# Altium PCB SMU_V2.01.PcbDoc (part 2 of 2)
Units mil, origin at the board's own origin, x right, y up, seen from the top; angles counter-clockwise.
Board outline 8661.42 x 7437.01 mil, 4 copper layers (Component Side, Ground Plane, Power Plane, Solder Side), stack 33.234 mil thick; 247 components, 163 nets, 805 pads, 762 vias.
Unrouted connection lines stored in the file: 6.
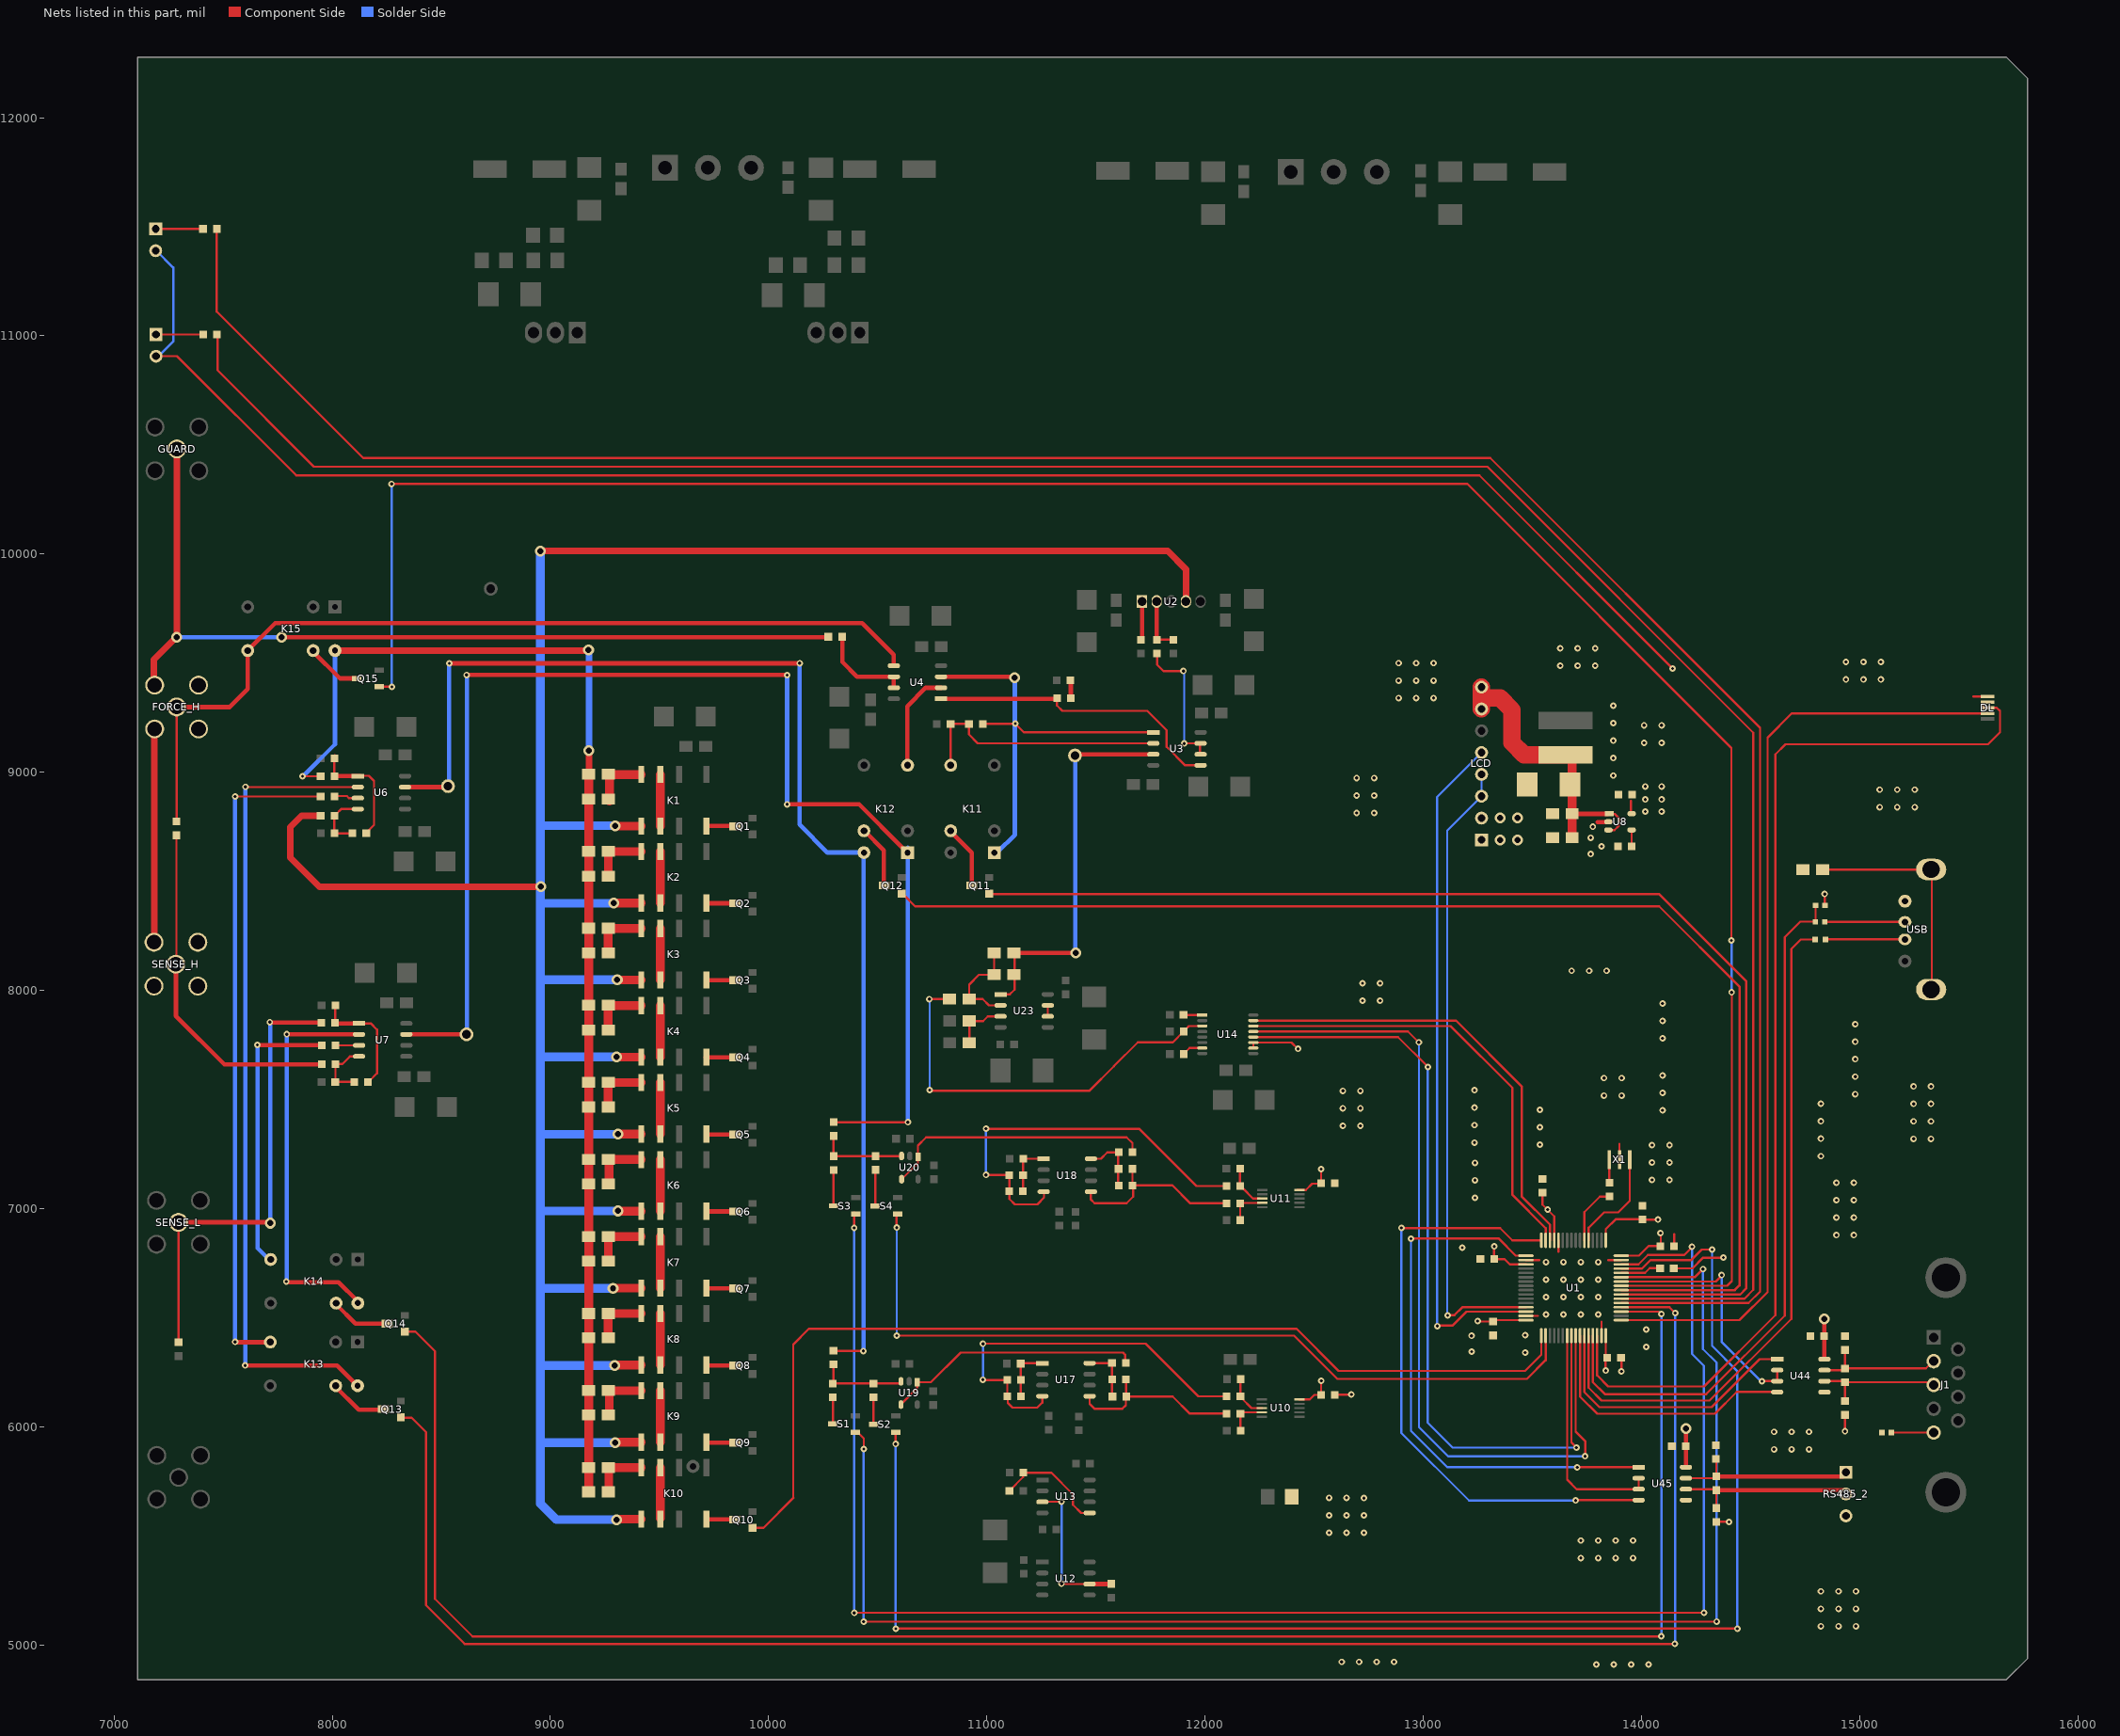
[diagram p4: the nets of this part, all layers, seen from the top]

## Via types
v1: diameter 30/30 (per signal layer), hole 14, Component Side to Solder Side, 662 vias
v2: diameter 50, hole 28, Component Side to Solder Side, 70 vias
v3: diameter 30, hole 14, Component Side to Solder Side, 26 vias
v4: diameter 39.37, hole 29.53, Component Side to Solder Side, 2 vias
v5: diameter 66.93, hole 47.24, Component Side to Solder Side, 2 vias

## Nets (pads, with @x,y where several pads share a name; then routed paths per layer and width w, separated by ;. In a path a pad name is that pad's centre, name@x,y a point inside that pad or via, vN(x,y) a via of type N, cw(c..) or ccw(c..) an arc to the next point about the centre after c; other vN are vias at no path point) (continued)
CTRL10: Q10.1 U1.33 | length 4625.3
  Component Side w10: Q10.1@9920.57,5537.65 9976.4,5537.65 10113.13,5674.38 ; Q10.1@9922.12,5537.11 Q10.1@9922.12,5551.99 ; 10112.55,5673.29 10112.55,6377.54 10185.04,6450.03 12418.3,6450.03 12612.01,6256.32 13466.42,6256.32 13540.97,6330.87 U1.33@13540.97,6418.24
CTRL11: Q11.1 U1.55 | length 5625.4
  Component Side w10: Q11.1@11014.47,8436.12 11020.61,8442.25 14080.45,8442.25 14478.93,8043.78 14478.93,8042.97 14479.29,8042.61 14479.29,6633.68 14452.82,6607.22 U1.55@13907.11,6607.22
CTRL12: Q12.1 U1.56 | length 5930.3
  Component Side w10: Q12.1@10614.72,8442.38 10671.36,8385.73 14080.95,8385.74 14449,8017.69 14449,6648.43 14427.48,6626.9 U1.56@13907.11,6626.9
CTRL13: Q13.1 U1.52 | length 8504
  Component Side w10: Q13.1@8316.05,6042.29 8363.72,6042.29 8429.56,5976.45 8429.56,5182.38 8606.5,5005.45 v3@14152.06,5005.45 ; U1.52@13907.11,6548.16 14128.51,6548.16 v3@14154.38,6522.29
  Solder Side w10: v3@14154.38,5005.85 v3(14154.38,6521.19)
  other v3: 14152.57,5005.85
CTRL14: Q14.1 U1.51 | length 8666.1
  Component Side w10: Q14.1@8326.42,6436.35 8381.6,6436.35 8470.69,6347.26 8470.69,5212.23 8643.14,5039.78 14081.06,5039.78 v3@14091.75,5050.47 ; U1.51@13907.11,6528.48 14079.18,6528.48 v3@14089.4,6518.25
  Solder Side w10: v3@14091.54,5050.7 v3(14091.54,6517.14)
  other v3: 14090.71,5040.17
CTRL15: Q15.1 U1.57 | length 10596.9
  Component Side w10: Q15.1@8214.96,9392.83 v3@8277.84,9392.83 ; v3(8272.01,10321.59) 13202.4,10321.59 14412.19,9111.8 v1@14412.19,8228.18 ; U1.57@13907.11,6646.59 14392.55,6646.59 14413.69,6667.73 v1@14413.69,7988.82
  Solder Side w10: v3(8272.93,9391.66) v3@8272.93,10323.43 ; v1(14413.05,7991.51) v1@14413.05,8232.41
  other v1: 14412.19,8229.76
D1: K1.8 Q1.3 | length 133.6
  Component Side w20: K1.8@9715.55,8753.74 Q1.3@9849.19,8753.74
D2: K2.8 Q2.3 | length 130.3
  Component Side w20: K2.8@9715.03,8399.71 Q2.3@9845.34,8399.71
D3: K3.8 Q3.3 | length 130.4
  Component Side w20: K3.8@9714.93,8046.63 Q3.3@9845.34,8046.63
D3V3: C1.2 C2.2 C3.2 C4.2 C5.2 C6.2 C22.2 C29.2 C81.2 C85.2 C108.2 LED0.2 LED1.2 R42.1 R102.2 R105.2 U1.1 U1.13 U1.19 U1.32 U1.48 U1.64 U8.5 U10.10 U11.10 U14.10 U14.11 U44.8 U45.8 | length 10716.3
  Component Side w10: LED1.2@7176.54,10907.22 7288.28,10907.22 7835.2,10360.31 13256.88,10360.31 v1(14141.88,9475.31) ; U14.10@12221.05,7736.31 U14.11@12221.05,7758.94 ; U14.11@12226.3,7761.51 12395.95,7761.51 12424.84,7732.62 v1@12426.19,7732.62 ; U11.10@12421.52,7085.54 12461.73,7085.54 12490.94,7114.75 C85.2@12523.99,7114.75 ; U10.10@12432.09,6125.59 12479.89,6125.59 12500.92,6146.61 C81.2@12515.07,6146.61 ; C85.2@12531.5,7116.98 v1@12531.5,7175.83 ; C81.2@12531.71,6147.25 v1@12531.71,6210.47 ; v1@13245.25,6482.49 C6.2@13319.59,6482.49 ; C2.2@13312.76,6768.97 13372.99,6768.97 13396.94,6745.01 U1.19@13470.11,6745.01 ; C6.2@13319.59,6489.11 U1.32@13470.11,6489.11 ; C2.2@13324.77,6770.14 v1@13324.77,6828.08 ; C1.2@13546.28,7074.6 13546.28,7018.74 13600.03,6964.99 U1.13@13600.03,6855.25 ; v1(13835.74,6258.05) C5.2@13835.74,6314.15 ; C5.2@13836.25,6305.29 U1.48@13836.25,6418.24 ; U1.1@13836.25,6855.25 13836.25,6906.38 13881.15,6951.29 C4.2@14009.16,6951.29 ; U1.64@13907.11,6784.38 13987.94,6784.38 14032.89,6829.34 C3.2@14084.69,6829.34 ; U8.5@13950.9,8809.48 13950.9,8869.84 ; C4.2@14003.81,6950.29 v1@14078.83,6950.29 ; C3.2@14088.76,6836.88 v1@14088.76,6883.52 ; R105.2@14342.63,5565.07 v1@14398.65,5565.07 ; v2(14838.42,6495.31) v2@14838.42,6508.77 ; R42.1@14839.75,8391.23 v1(14839.75,8442.22) ; v1(14932.63,5979.56) R102.2@14932.63,6055.07
  Component Side w20: U45.8@14203.42,5815.31 v2(14203.42,5991.84) ; U44.8@14838.42,6310.31 v2(14838.42,6495.31)
  Solder Side w10: LED1.2@7192.45,10906.75 7203.88,10906.75 7271.25,10974.11 7271.25,11313 LED0.2@7193.23,11391.03
  other v1: 14401.39,5564.22 12532.32,6210.98 13248.99,6485.31 13325.59,6826.87 14087.17,6887.98 14075.08,6949.95 13569.87,6996 12531.7,7180.98 12426.15,7732.55 14016.88,8820.31 14091.88,8820.31 14016.88,8875.31 14091.88,8875.31 14016.88,8935.31 14091.88,8935.31
D4: K4.8 Q4.3 | length 133.8
  Component Side w20: K4.8@9711.55,7693.54 Q4.3@9845.34,7693.54
D5: K5.8 Q5.3 | length 132.6
  Component Side w20: K5.8@9712.77,7340.46 Q5.3@9845.34,7340.46
D5V0: C57.2 C58.2 C59.1 L2.2 LCD.7 LCD.8 U8.1 U8.3 | length 1367.8
  Component Side w10: U8.3@13844.6,8734.68 13876.25,8734.68 13896.88,8755.31 13896.88,8790.31 13877.71,8809.48 U8.1@13844.6,8809.48
  Component Side w22: C58.2@13682.71,8809.48 U8.1@13844.6,8809.48
  Component Side w40: C57.2@13682.34,8700.76 13682.34,8935.31 L2.2@13682.34,9070.07
  Component Side w80: LCD.7@13266.88,9290.31 LCD.8@13266.88,9390.31 ; 13266.88,9340.31 13351.88,9340.31 13406.88,9285.31 13406.88,9135.31 13461.88,9080.31 L2.2@13651.88,9080.31
D6: K6.8 Q6.3 | length 126.8
  Component Side w20: K6.8@9718.57,6987.37 Q6.3@9845.34,6987.37
D7: K7.8 Q7.3 | length 128.9
  Component Side w20: K7.8@9716.44,6634.29 Q7.3@9845.34,6634.29
D8: K8.8 Q8.3 | length 127
  Component Side w20: K8.8@9718.38,6281.21 Q8.3@9845.34,6281.21
D9: K9.8 Q9.3 | length 132
  Component Side w20: K9.8@9713.35,5928.12 Q9.3@9845.34,5928.12
D10: K10.8 Q10.3 | length 128
  Component Side w20: K10.8@9715.55,5576.99 Q10.3@9843.53,5576.99
D11: K11.5 Q11.3 | length 272.2
  Component Side w10: K11.5@10834.46,8728.35 K11.5@10834.46,8732.05
  Component Side w20: K11.5@10834.46,8728.35 10930.62,8632.19 Q11.3@10930.62,8499.67
D12: K12.5 Q12.3 | length 284.1
  Component Side w10: K12.5@10436.55,8732.05 K12.5@10438.01,8732.05
  Component Side w20: K12.5@10438.01,8732.05 10528.04,8642.01 Q12.3@10528.04,8486.75
D13: K13.5 Q13.3 | length 267.4
  Component Side w10: K13.5@8014.82,6185.08 K13.5@8014.82,6187.86
  Component Side w20: K13.5@8014.82,6185.08 8120.68,6079.23 Q13.3@8235.57,6079.23
D14: K14.5 Q14.3 | length 284.6
  Component Side w20: K14.5@8016.68,6562.69 8106.59,6472.77 Q14.3@8264.05,6472.77
D15: K15.5 Q15.3 | length 253.5
  Component Side w20: K15.5@7910.7,9554.75 8035.22,9430.23 Q15.3@8112.6,9430.23
DAC1_FSYNC: U1.41 U14.13 | length 3927.6
  Component Side w10: U14.13@12222.43,7811.9 12929.54,7811.9 v1@12979.23,7762.21 ; U1.41@13698.45,6418.24 13698.45,5978.74 13741.88,5935.31 v1(13741.88,5865.31)
  Solder Side w10: v1@12980.14,7761.37 12980.14,5999.26 13114.08,5865.31 v1(13741.88,5865.31)
  other v1: 12979.57,7762.59
DAC1_RESET: U1.14 U14.15 | length 2110.4
  Component Side w10: U14.15@12224.6,7862.29 13149.46,7862.29 13450.72,7561.03 13450.72,7056.85 13580.34,6927.22 U1.14@13580.34,6855.25
DAC1_SCLK: U1.40 U14.12 | length 3735.5
  Component Side w10: U14.12@12224.06,7786.7 12884.54,7786.7 v1@13020.01,7651.24 ; U1.40@13678.77,6418.24 13678.77,5928.43 v1(13701.88,5905.31)
  Solder Side w10: v1@13020.04,7651.46 13020.04,6019.85 13134.58,5905.31 v1(13701.88,5905.31)
  other v1: 13020.67,7649.88
DAC1_SDATA: U1.15 U14.14 | length 2059.5
  Component Side w10: U14.14@12225.14,7837.1 13125.18,7837.1 ; 13127.08,7835.11 13408.8,7553.4 13408.8,7062.49 13560.66,6910.63 U1.15@13560.66,6855.25
DGND: C1.1 C2.1 C3.1 C4.1 C5.1 C6.1 C22.1 C23.1 C29.1 C57.1 C58.1 C59.2 C81.1 C85.1 C108.1 DL.5 L1.2 L3.2 LCD.1 LCD.2 R2.2 R66.1 R101.2 R104.2 RS485_2.3 U1.12 U1.18 U1.31 U1.47 U1.63 U8.2 U44.5 U45.5 USB.4 X1.2 | length 897.6
  Component Side w10: C81.1@12594.7,6147.25 v1@12672.07,6147.25 ; U1.31@13470.11,6508.79 13525.37,6508.79 ; U1.18@13470.11,6764.7 13531.27,6764.7 ; 13619.71,6802.48 U1.12@13619.71,6855.25 ; U1.47@13816.56,6418.24 13816.56,6481.79 ; 13847.49,6764.7 U1.63@13907.11,6764.7 ; X1.2@13899.11,7225.16 13899.11,7297.18 ; v1(13907.96,6253.87) C5.1@13907.96,6317.13 ; C3.1@14149.66,6828.63 14149.66,6882.15 ; 14166.08,6726.9 14233.71,6726.9 14282.33,6775.51 v1@14373.8,6775.51 ; 15520.28,9346.96 DL.5@15585.53,9346.96
  Component Side w20: 13798.66,8772.08 U8.2@13844.6,8772.08
  other v1: 13792.56,4911.52 13872.56,4911.52 13952.56,4911.52 14032.56,4911.52 12625.86,4923 12705.86,4923 12785.86,4923 12865.86,4923 14822.53,5086.38 14902.53,5086.38 14982.53,5086.38 14822.53,5166.38 14902.53,5166.38 14982.53,5166.38 14822.53,5246.38 14902.53,5246.38 14982.53,5246.38 13721.63,5399.14 13801.63,5399.14 13881.63,5399.14 13961.63,5399.14 13721.63,5479.14 13801.63,5479.14 13881.63,5479.14 13961.63,5479.14 12568.37,5515.09 12648.37,5515.09 12728.37,5515.09 12568.37,5595.09 12648.37,5595.09 12728.37,5595.09 12728.25,5673.54 12568.37,5675.09 12648.37,5675.09 14607.34,5897.3 14687.34,5897.3 14767.34,5897.3 14607.34,5977.3 14687.34,5977.3 14767.34,5977.3 12670.6,6148.64 13466.88,6340.31 13221.75,6344.34 14021.33,6366.39 13220.96,6417.42 13466.88,6420.31 14021.33,6446.39 13561.88,6515.31 13641.88,6515.31 13721.88,6515.31 13801.88,6515.31 13561.88,6595.31 13641.88,6595.31 13721.88,6595.31 13801.88,6595.31 13561.88,6675.31 13641.88,6675.31 13721.88,6675.31 13801.88,6675.31 13561.88,6755.31 13641.88,6755.31 13721.88,6755.31 13801.88,6755.31 14374.93,6776.65 13178.69,6821.71 14893.33,6879.01 14973.33,6879.01 14893.33,6959.01 14973.33,6959.01 14893.33,7039.01 14973.33,7039.01 13236.88,7050.31 14893.33,7119.01 14973.33,7119.01 13236.88,7130.31 14048.35,7131.47 14128.35,7131.47 13236.88,7210.31 14048.35,7211.47 14128.35,7211.47 14822.19,7240.68 14048.35,7291.47 14128.35,7291.47 13534.13,7293.67 13234.52,7303.01 15246.88,7320.31 15326.88,7320.31 14822.19,7320.68 13534.13,7373.67 12631.88,7380.31 12711.88,7380.31 13234.52,7383.01 15246.88,7400.31 15326.88,7400.31 14822.19,7400.68 14096.2,7450.86 13534.13,7453.67 12631.88,7460.31 12711.88,7460.31 13234.52,7463.01 15246.88,7480.31 15326.88,7480.31 14822.19,7480.68 13828.57,7518.66 13908.57,7518.66 14979.77,7525.18 14096.2,7530.86 12631.88,7540.31 12711.88,7540.31 13234.52,7543.01 15246.88,7560.31 15326.88,7560.31 13828.57,7598.66 13908.57,7598.66 14979.77,7605.18 14096.2,7610.86 14979.77,7685.18 14979.77,7765.18 14096.2,7780.86 14979.77,7845.18 14096.2,7860.86 14096.2,7940.86 12721.88,7953.43 12801.88,7953.43 12721.88,8033.43 12801.88,8033.43 13679.84,8090.23 13759.84,8090.23 13839.84,8090.23 13766.88,8625.31 13816.88,8660.31 13766.88,8700.31 13776.88,8750.31 12694.62,8813.79 12774.62,8813.79 15091.88,8840.31 15171.88,8840.31 15251.88,8840.31 12694.62,8893.79 12774.62,8893.79 15091.88,8920.31 15171.88,8920.31 15251.88,8920.31 12694.62,8973.79 12774.62,8973.79 13870.46,8985.13 13870.46,9065.13 14011.88,9135.31 14091.88,9135.31 13870.46,9145.13 14011.88,9215.31 14091.88,9215.31 13870.46,9225.13 13870.46,9305.13 12886.88,9340.31 12966.88,9340.31 13046.88,9340.31 12886.88,9420.31 12966.88,9420.31 13046.88,9420.31 14936.88,9425.31 15016.88,9425.31 15096.88,9425.31 13627.78,9488.72 13707.78,9488.72 13787.78,9488.72 12886.88,9500.31 12966.88,9500.31 13046.88,9500.31 14936.88,9505.31 15016.88,9505.31 15096.88,9505.31 13627.78,9568.72 13707.78,9568.72 13787.78,9568.72
  other v2: 13351.88,8690.31 13431.88,8690.31 13351.88,8790.31 13431.88,8790.31
DUT_VOLTAGE: K12.1 R51.2 T2.1 U7.7 | length 6180.8
  Component Side w10: R51.2@10297.56,7396.42 v3@10634.24,7396.42
  Component Side w20: U7.7@8339.58,7798.88 T2.1@8615.03,7798.88 ; v3(8615.67,9446.19) v3@10079.09,9446.19 ; v3(10084.09,8853.31) 10414.46,8853.31 K12.1@10611.71,8656.06
  Solder Side w20: T2.1@8616.66,7799.23 v3@8616.66,9446.22 ; v3@10084.41,8856.18 v3(10084.41,9445.92) ; v3@10637.68,7394.96 K12.1@10637.68,8654.16
  other v3: 10637.98,7396.46
FB_R_T1: C70.1 C71.1 C72.1 C73.1 C74.1 C75.1 C76.1 C77.1 C78.1 C79.1 K15.6 R19.2 R31.1 R32.1 R33.1 R34.1 R35.1 R36.1 R37.1 R38.1 R39.1 R40.1 | length 5739.7
  Component Side w10: v3@7867.94,8981.55 R19.2@7948.53,8981.55
  Component Side w30: K15.6@8012.65,9557.88 v2@9173.85,9557.88 ; R31.1@9171.24,8985.77 9176.58,8991.11 v2(9176.56,9099.22)
  Component Side w40: C79.1@9175.42,5705.38 R40.1@9175.42,5813.12 C78.1@9175.42,6055.22 R39.1@9175.42,6166.28 C77.1@9175.42,6407.94 R38.1@9175.42,6519.44 C76.1@9175.42,6760.67 R37.1@9175.42,6872.6 C75.1@9175.42,7113.4 R36.1@9175.42,7225.76 C74.1@9175.42,7466.13 R35.1@9175.42,7578.92 C73.1@9175.42,7818.86 R34.1@9175.42,7932.09 C72.1@9175.42,8171.58 R33.1@9175.42,8285.25 C71.1@9175.42,8524.31 R32.1@9175.42,8638.41 C70.1@9175.42,8877.04 R31.1@9175.42,8991.57
  Solder Side w20: v3@7866.28,8982.22 8012.65,9128.59 K15.6@8012.65,9557.88
  Solder Side w30: v2@9175.92,9558.76 9176.56,9558.12 v2(9176.56,9099.22)
  other v2: 9174.48,9560.15
  other v3: 7864.07,8981.28
FB_R_T2: K1.5 K2.5 K3.5 K4.5 K5.5 K6.5 K7.5 K8.5 K9.5 K10.5 R21.2 U2.4 | length 13617.1
  Component Side w30: R21.2@7939.8,8801.07 7860.21,8801.07 7808.19,8749.06 7808.19,8607.99 7941.02,8475.16 v2@8953.23,8475.16 ; v2@8955.66,10013.74 11828.42,10013.74 11911.99,9930.18 U2.4@11911.99,9782.7
  Component Side w40: v2@9287.6,6635.91 K7.5@9416.34,6635.91 ; v2@9288.99,8400.76 K2.5@9416.34,8400.76 ; v2@9289.28,6282.93 K8.5@9416.34,6282.93 ; v2@9296.82,5929.96 K9.5@9416.34,5929.96 ; v2@9297.25,7694.82 K4.5@9416.34,7694.82 ; v2@9298.95,8753.74 K1.5@9416.34,8753.74 ; v2@9304.27,5576.99 K10.5@9416.34,5576.99 ; v2@9307.92,8047.79 K3.5@9416.34,8047.79 ; v2@9309.83,6988.88 K6.5@9416.34,6988.88 ; v2@9314.01,7341.85 K5.5@9416.34,7341.85
  Solder Side w40: v2@8953.9,10014.45 8953.9,6989.61 ; 8954.79,8755.61 v2@9300.6,8755.61 ; 8956.15,6281.23 v2(9293.52,6281.23) ; 8957.46,6634.94 v2(9286.79,6634.94) ; 8960.46,7695.1 v2(9303.13,7695.1) ; 8960.49,8399.92 v2(9289.6,8399.92) ; 8962.72,8049.77 v2(9306.02,8049.77) ; 8963.99,7341.39 v2(9308.9,7341.39) ; v2(9296.41,5927.52) 8953.9,5927.52 ; v2(9303.13,5574.77) 9027.3,5574.77 8953.9,5648.16 8953.9,5927.52 ; v2(9308.9,6989.61) 8953.9,6989.61 ; 8953.9,5927.52 8953.9,6989.61
  other v2: 8956.65,8475.63 9296.1,8754.49 8953.63,10013.91
FH_OUT: FORCE_H.1 K15.4 R76.1 U4.5 | length 4177.8
  Component Side w10: R76.1@7286.86,8778.52 FORCE_H.1@7286.86,9298.99 ; K15.4@7612.65,9557.88 K15.4@7612.9,9558.12
  Component Side w20: FORCE_H.1@7286.86,9298.99 7530.07,9298.99 7612.9,9381.82 7612.9,9558.12 7738.67,9683.9 10427.91,9683.9 10572.74,9539.06 U4.5@10572.74,9490.63
GUARD: FORCE_H.2 GUARD.1 R28.2 SENSE_H.2 | length 5137.4
  Component Side w10: SENSE_H.2@7175.5,8220.98 SENSE_H.2@7184.03,8220.98 ; SENSE_H.2@7383.96,8011.56 SENSE_H.2@7383.96,8020.19
  Component Side w20: v2@7762.69,9619.66 R28.2@10273.67,9619.66
  Component Side w30: FORCE_H.2@7177.03,9209.76 7184.03,9202.76 SENSE_H.2@7184.03,8220.98 ; FORCE_H.2@7182.05,9394.91 7182.05,9516.65 7288.07,9622.67 GUARD.1@7288.07,10482.17
  Solder Side w20: v2@7282.04,9619.6 v2(7768.41,9619.6)
  other v2: 7287.71,9619.68
LED0: R68.2 U1.53 | length 11483.7
  Component Side w10: R68.2@7470.77,11490.82 7470.77,11111.24 8141.7,10440.31 13306.88,10440.31 14543.28,9203.91 14543.28,6620.21 14490.92,6567.85 U1.53@13907.11,6567.85
LED1: R69.2 U1.54 | length 11066.6
  Component Side w10: R69.2@7474.11,11007.05 7474.11,10842.18 7915.98,10400.31 13293.67,10400.31 14512.4,9181.58 14512.4,6628.06 14471.87,6587.53 U1.54@13907.11,6587.53
NetC7_1: C7.1 R46.2 U10.4 | length 184.1
  Component Side w10: C7.1@12161.61,5985.45 12161.61,6066.65 U10.4@12264.51,6066.65
NetC8_1: C8.1 R47.2 U11.4 | length 161.1
  Component Side w10: C8.1@12160.93,6944.16 R47.2@12160.93,7023.76 ; R47.2@12168.75,7026.48 U11.4@12250.26,7026.48
NetC20_2: C20.2 R10.2 U2.2 | length 254.1
  Component Side w10: R10.2@11779.77,9607.52 C20.2@11855.36,9607.52
  Component Side w20: R10.2@11777.83,9608.74 U2.2@11777.83,9787.27
NetC21_1: C21.1 R16.2 | length 86.5
  Component Side w20: R16.2@11384.47,9333.72 C21.1@11384.47,9420.26
NetC23_2: C23.2 U8.4 | length 72.4
  Component Side w10: C23.2@13954.72,8663.27 U8.4@13954.72,8735.63
NetC30_1: C30.1 C31.2 R19.1 U6.1 | length 516.8
  Component Side w10: C31.2@8008.6,9074.08 C31.2@8011.71,9077.19 ; R19.1@8009.95,8982.56 C31.2@8009.95,9064.12 ; U6.1@8125.98,8984.01 8167.34,8984.01 8191.55,8959.8 8191.55,8758.68 C30.1@8165.54,8732.67
  Component Side w20: R19.1@8009.13,8982.4 U6.1@8126.51,8982.4
NetC30_2: C30.2 C32.1 R21.1 U6.4 | length 259.9
  Component Side w10: C32.1@8009.83,8726.33 R21.1@8009.83,8801.5 ; C32.1@8010.35,8719.3 C30.2@8086.3,8719.3 ; R21.1@8017.78,8808.57 8040.53,8831.32 U6.4@8117.1,8831.32
NetC33_2: C33.2 C34.1 R12.2 U7.1 | length 540.5
  Component Side w10: R12.2@8013.26,7852.35 C33.2@8013.26,7934.4 ; U7.1@8123.04,7849.28 8176.02,7849.28 8204.98,7820.32 8204.98,7619.79 C34.1@8166.55,7581.36
  Component Side w20: R12.2@8004.77,7848.98 U7.1@8114.44,7848.98
NetC34_2: C34.2 C35.1 R14.2 U7.4 | length 294.3
  Component Side w10: C34.2@8103.05,7581.03 8014.33,7581.03 R14.2@8014.33,7662.74 8045.95,7662.74 8080.5,7697.29 U7.4@8123.86,7697.29
NetC49_1: C49.1 U14.1 | length 87.2
  Component Side w10: C49.1@11899.97,7887.49 U14.1@11987.2,7887.49
NetC70_2: C70.2 K1.4 R31.2 | length 267.6
  Component Side w40: C70.2@9270.78,8867.93 9270.78,8989.96 K1.4@9416.34,8989.96
NetC71_2: C71.2 K2.4 R32.2 | length 252.5
  Component Side w40: C71.2@9265.42,8526.63 R32.2@9265.42,8638.41 ; R32.2@9275.65,8636.98 K2.4@9416.34,8636.98
NetC72_2: C72.2 K3.4 R33.2 | length 255.1
  Component Side w10: C72.2@9263.99,8196.39 C72.2@9274.69,8185.68
  Component Side w40: C72.2@9263.99,8196.39 9263.99,8284.01 K3.4@9416.34,8284.01
NetC73_2: C73.2 K4.4 R34.2 | length 262.3
  Component Side w10: C73.2@9264.32,7822.44 C73.2@9265.53,7821.24
  Component Side w40: C73.2@9264.32,7822.44 9264.32,7931.04 K4.4@9416.34,7931.04
NetC74_2: C74.2 K5.4 R35.2 | length 262.6
  Component Side w40: C74.2@9263.58,7468.25 9263.58,7578.07 K5.4@9416.34,7578.07
NetC75_2: C75.2 K6.4 R36.2 | length 264.2
  Component Side w10: R36.2@9268.3,7224.97 R36.2@9268.43,7225.1
  Component Side w40: C75.2@9268.3,7108.84 R36.2@9268.3,7224.97 ; R36.2@9268.43,7225.1 K6.4@9416.34,7225.1
NetC76_2: C76.2 K7.4 R37.2 | length 260.5
  Component Side w40: C76.2@9265.3,6762.64 9265.3,6872.13 K7.4@9416.34,6872.13
NetC77_2: C77.2 K8.4 R38.2 | length 260
  Component Side w40: C77.2@9264.02,6411.52 9264.02,6519.15 K8.4@9416.34,6519.15
NetC78_2: C78.2 K9.4 R39.2 | length 253.3
  Component Side w40: C78.2@9269.23,6060.03 9269.23,6166.18 K9.4@9416.34,6166.18
NetC79_2: C79.2 K10.4 R40.2 | length 257.4
  Component Side w40: C79.2@9267.22,5704.95 9267.22,5813.21 K10.4@9416.34,5813.21
NetC80_1: C80.1 R30.2 U10.3 | length 195.8
  Component Side w10: R30.2@12162.1,6140.26 C80.1@12162.1,6222.68 ; R30.2@12166.49,6132.16 12212.44,6086.22 U10.3@12260.83,6086.22
NetC84_2: C84.2 R29.2 U11.3 | length 179.5
  Component Side w10: R29.2@12160.35,7102.94 C84.2@12160.35,7183.14 ; R29.2@12171.14,7094.85 12219.83,7046.17 U11.3@12250.26,7046.17
NetC90_2: C90.2 U12.6 U13.3 | length 672.7
  Component Side w10: U13.3@11249.53,5657.3 v1@11335.08,5657.3 ; 11360.47,5280.02 U12.6@11470.55,5280.02
  Component Side w20: U12.6@11470.55,5280.02 C90.2@11570.77,5280.02
  Solder Side w10: v1(11342.2,5280.94) v1@11342.2,5657.74
  other v1: 11342.55,5657.21
NetC122_1: C122.1 R46.1 R54.2 U17.5 | length 828.9
  Component Side w10: U17.5@11470.57,6140.8 11470.57,6105.43 11492.51,6083.49 11621.18,6083.49 11636.95,6099.25 C122.1@11636.95,6140.58 ; C122.1@11637.25,6138.74 11851.89,6138.74 11929.86,6060.77 R46.1@12097.73,6060.77 ; C122.1@11637.7,6139.96 R54.2@11637.7,6217.36
NetC122_2: C122.2 R53.1 R54.1 U17.8 | length 255.1
  Component Side w10: U17.8@11469.57,6291.56 R53.1@11571.84,6291.56 ; C122.2@11573.4,6140.38 R53.1@11573.4,6293.23
NetC123_1: C123.1 R30.1 R56.2 U17.4 | length 1806
  Component Side w10: v1@10984.23,6214.7 R56.2@11093.33,6214.7 C123.1@11093.33,6133.36 ; v1@10984.61,6381.37 11728.03,6381.37 11969.15,6140.26 R30.1@12099.11,6140.26 ; C123.1@11095.85,6139.42 11095.85,6110.14 11117.64,6088.35 11230.81,6088.35 11254.04,6111.58 U17.4@11254.04,6140.8
  Solder Side w10: v1@10982.27,6214.81 10982.32,6214.87 v1(10982.32,6380.68)
  other v1: 10981.49,6216.15
NetC123_2: C123.2 R55.2 R56.1 U17.1 | length 240.2
  Component Side w10: C123.2@11155.27,6140.93 R55.2@11155.27,6289.84 ; R55.2@11162.72,6291.99 U17.1@11254.04,6291.99
NetC124_1: C124.1 R47.1 R58.2 U18.5 | length 829.4
  Component Side w10: U18.5@11476.92,7077.81 11476.92,7041.79 11493.33,7025.37 11640.17,7025.37 11670.21,7055.42 C124.1@11670.21,7105.31 ; C124.1@11666.77,7108.98 R58.2@11666.77,7182.29 ; C124.1@11667.39,7106.62 11849.86,7106.62 11930.7,7025.77 R47.1@12091.55,7025.77
NetC124_2: C124.2 R57.1 R58.1 U18.8 | length 285.2
  Component Side w10: U18.8@11476.92,7228.99 11522.9,7228.99 11551.66,7257.75 11601.49,7257.75 C124.2@11601.49,7109.04
NetC125_1: C125.1 R29.1 R60.2 U18.4 | length 1839.9
  Component Side w10: v1@10996.33,7366.43 11697.53,7366.43 11960.11,7103.85 R29.1@12098.16,7103.85 ; v1@10998.19,7153.92 R60.2@11102.96,7153.92 11102.96,7044.65 11127.94,7019.67 11231.06,7019.67 11261.96,7050.57 U18.4@11261.96,7078.19
  Solder Side w10: v1@10995.66,7161.56 v1(10995.66,7367.03)
  other v1: 10995.92,7154.75
NetC125_2: C125.2 R59.1 R60.1 U18.1 | length 241.5
  Component Side w10: R60.1@11162.98,7159.38 11165.68,7162.08 11165.68,7228.99 U18.1@11260.38,7228.99 ; C125.2@11165.95,7077.85 R60.1@11165.95,7153.92
NetC154_1: C154.1 R24.2 R25.1 U23.2 | length 452.6
  Component Side w10: R24.2@10918.59,7960.58 10918.59,8026.92 10963.38,8071.71 11032.55,8071.71 11033.61,8072.78 R25.1@11033.61,8172.08 ; R24.2@10921.81,7960.94 10980.3,7960.94 11009.32,7931.92 U23.2@11062.71,7931.92
NetJ1_2: J1.2 R100.1 R101.1 U44.7 | length 598
  Component Side w10: U44.7@14838.42,6259.91 R100.1@14929.48,6259.91 ; R101.1@14932.63,6352.55 R100.1@14932.63,6268.06 15303.67,6268.06 J1.2@15340.01,6304.4
NetJ1_3: J1.3 R100.2 R102.1 U44.6 | length 577.3
  Component Side w10: U44.6@14838.42,6209.52 R100.2@14933.18,6209.52 ; R102.1@14932.63,6118.06 R100.2@14932.63,6205.07 ; R100.2@14933.18,6205.07 J1.3@15328.72,6205.07
NetJ1_5: J1.5 R66.2 | length 190.3
  Component Side w10: R66.2@15148.68,5974.15 J1.5@15338.96,5974.15
NetK1_3: K1.3 K1.6 | length 239.2
  Component Side w10: K1.3@9502.95,8989.96 K1.3@9502.95,8992.97
  Component Side w40: K1.6@9502.95,8753.74 K1.3@9502.95,8989.96
NetK2_3: K2.3 K2.6 | length 236.2
  Component Side w40: K2.6@9502.95,8400.76 K2.3@9502.95,8636.98
NetK3_3: K3.3 K3.6 | length 243.5
  Component Side w10: K3.6@9502.95,8040.53 K3.6@9502.95,8047.79
  Component Side w40: K3.6@9502.95,8047.79 K3.3@9502.95,8284.01
NetK4_3: K4.3 K4.6 | length 238.4
  Component Side w10: K4.6@9502.95,7692.6 K4.6@9502.95,7694.82
  Component Side w40: K4.6@9502.95,7694.82 K4.3@9502.95,7931.04
NetK5_3: K5.3 K5.6 | length 238.2
  Component Side w10: K5.6@9502.95,7339.91 K5.6@9502.95,7341.85
  Component Side w40: K5.6@9502.95,7341.85 K5.3@9502.95,7578.07
NetK6_3: K6.3 K6.6 | length 238.7
  Component Side w10: K6.6@9502.95,6986.41 K6.6@9502.95,6988.88
  Component Side w40: K6.6@9502.95,6988.88 K6.3@9502.95,7225.1
NetK7_3: K7.3 K7.6 | length 243.2
  Component Side w10: K7.6@9502.95,6628.95 K7.6@9502.95,6635.91
  Component Side w40: K7.6@9502.95,6635.91 K7.3@9502.95,6872.13
NetK8_3: K8.3 K8.6 | length 237.3
  Component Side w10: K8.6@9502.95,6281.81 K8.6@9502.95,6282.93
  Component Side w40: K8.6@9502.95,6282.93 K8.3@9502.95,6519.15
NetK9_3: K9.3 K9.6 | length 240.2
  Component Side w10: K9.6@9502.95,5925.94 K9.6@9502.95,5929.96
  Component Side w40: K9.6@9502.95,5929.96 K9.3@9502.95,6166.18
NetK10_3: K10.3 K10.6 | length 232
  Component Side w40: K10.6@9502.95,5581.19 K10.3@9502.95,5813.21
NetK11_1: K11.1 R18.1 U3.1 U4.3 | length 1967.2
  Component Side w10: R18.1@10980.96,9221.85 v1@11124.29,9221.85 ; v1@11129.78,9222.57 11169.24,9183.11 U3.1@11762.79,9183.11
  Component Side w20: U4.3@10789.97,9437.78 v2@11129.97,9437.78
  Solder Side w20: K11.1@11050.16,8636.03 11128.37,8714.24 v2@11128.37,9438.15
  other v1: 11129.92,9223.33
  other v2: 11126.63,9432.66
NetK11_4: K11.4 R17.1 R18.2 U3.2 | length 1169.7
  Component Side w10: K11.4@10833.6,9041.19 R17.1@10833.6,9216.34 ; R17.1@10833.6,9221.7 R18.2@10921.57,9221.7 ; R18.2@10917.57,9217.89 10917.57,9173.36 10958.21,9132.71 U3.2@11762.79,9132.71
NetK12_3: K12.3 U4.2 | length 463.6
  Component Side w20: K12.3@10634.78,9029.12 10634.78,9302.37 10719.8,9387.39 U4.2@10789.97,9387.39
NetK13_3: K13.3 R44.1 | length 3057.3
  Component Side w10: v3@7556.04,8889.46 R44.1@7949.27,8889.46
  Component Side w20: v3@7551.15,6387.86 K13.3@7714.82,6387.86
  Solder Side w20: v3(7554.75,8888.66) 7554.75,6389.81 v3@7555.85,6388.71
  other v3: 7554.86,6389.41
NetK14_3: K14.3 R45.1 | length 1298.9
  Component Side w20: v3@7662.43,7749.31 R45.1@7951.61,7749.31
  Solder Side w20: v3@7657.53,7747.78 7657.53,6819.38 K14.3@7715,6761.91
  other v3: 7656.67,7750.58
NetL1_1: L1.1 USB.5 USB.6 | length 1034.6
  Component Side w10: L1.1@14834.53,8554.39 USB.5@15319.17,8554.39 ; USB.6@15330.03,8004.39 USB.5@15330.03,8554.39
NetLED0_1: LED0.1 R68.1 | length 213.9
  Component Side w10: LED0.1@7190.85,11490.63 R68.1@7404.72,11490.63
NetLED1_1: LED1.1 R69.1 | length 216.5
  Component Side w10: LED1.1@7192.45,11006.75 R69.1@7408.95,11006.75
NetR1_1: R1.1 X1.3 | length 103.8
  Component Side w10: R1.1@13851.87,7121.39 X1.3@13851.87,7225.16
NetR1_2: R1.2 U1.6 | length 275.5
  Component Side w10: U1.6@13737.82,6855.25 13737.82,6984.11 13809.19,7055.48 R1.2@13854.91,7055.48
NetR2_1: R2.1 U1.60 | length 185.9
  Component Side w10: U1.60@13907.11,6705.64 14016.33,6705.64 14037.95,6727.26 R2.1@14084.02,6727.26
NetR10_1: R10.1 U3.6 U3.7 | length 623.7
  Component Side w10: R10.1@11780.27,9541.92 11780.27,9493.19 11809.43,9464.03 v1(11900.76,9464.03) ; v1@11908.05,9132.64 11977.14,9132.64 U3.6@11977.14,9087.96
  Solder Side w10: v1(11904.35,9131.95) v1@11904.35,9460.63
NetR16_1: R16.1 U3.5 U4.1 | length 1375.2
  Component Side w10: R16.1@11321.28,9335.61 11321.28,9305.92 11345.54,9281.65 11734.63,9281.65 11824.12,9192.16 11824.12,9116.82 11909.02,9031.92 U3.5@11979.33,9031.92
  Component Side w20: U4.1@10789.97,9336.99 R16.1@11319.75,9336.99
NetR22_2: R22.2 R23.2 U23.3 | length 248.9
  Component Side w10: R23.2@10919.65,7762.56 R22.2@10919.65,7860.77 ; R22.2@10920.93,7859.95 10982.92,7859.95 11004.49,7881.52 U23.3@11062.71,7881.52
NetR27_2: R27.2 U2.1 | length 163.8
  Component Side w20: R27.2@11711.2,9618.9 U2.1@11711.2,9782.7
NetR28_1: R28.1 U4.6 U4.7 | length 410.6
  Component Side w20: R28.1@10337.44,9608.59 10337.44,9505.73 10405.39,9437.78 U4.6@10573.43,9437.78 U4.7@10573.43,9394.15
NetR41_1: R41.1 USB.3 | length 368.9
  Component Side w10: R41.1@14839.88,8314.28 USB.3@15208.81,8314.28
NetR43_1: R43.1 USB.2 | length 362.1
  Component Side w10: R43.1@14844.26,8234.28 USB.2@15206.37,8234.28
NetR49_1: R49.1 R50.2 R136.2 U19.3 | length 390.6
  Component Side w10: R50.2@10294.43,6198.87 U19.3@10602.14,6198.87 ; R50.2@10296.72,6204.09 R49.1@10296.72,6286.98
NetR50_1: R50.1 S1.3 | length 122.4
  Component Side w10: S1.3@10294.43,6013.44 R50.1@10294.43,6135.87
NetR51_1: R51.1 R52.2 R137.2 U20.3 | length 388.4
  Component Side w10: R52.2@10297.56,7240.8 R137.2@10484.18,7240.8 ; R52.2@10297.56,7248.32 R51.1@10297.56,7333.43 ; R137.2@10489.17,7240.99 U20.3@10605.83,7240.99
NetR52_1: R52.1 S3.3 | length 162
  Component Side w10: S3.3@10297.34,7012.34 R52.1@10297.34,7174.36
NetR53_2: R53.2 U19.1 U19.4 | length 1175.2
  Component Side w10: U19.4@10608.69,6106.02 10681.14,6178.47 U19.1@10681.14,6204.72 10743.7,6204.72 10879.67,6340.7 11623.67,6340.7 11634.1,6330.27 R53.2@11634.1,6297.4
NetR57_2: R57.2 U20.1 U20.4 | length 1234.3
  Component Side w10: U20.4@10609.3,7135.21 10683.57,7209.48 U20.1@10683.57,7238.98 ; U20.1@10684.1,7237.57 10684.1,7289.33 10722.01,7327.24 11640.65,7327.24 11667.04,7300.85 R57.2@11667.04,7262.43
NetR61_2: R61.2 R62.1 U13.5 | length 508.4
  Component Side w10: R61.2@11103.82,5707.87 11165.92,5769.96 R62.1@11165.92,5786.12 ; R62.1@11166.77,5790.37 11295.09,5790.37 11394.55,5690.91 11394.55,5643.1 11432.45,5605.19 U13.5@11466.46,5605.19
NetR103_1: R103.1 R104.1 RS485_2.1 U45.7 | length 790.1
  Component Side w10: U45.7@14203.42,5764.91 R103.1@14334.48,5764.91 ; R103.1@14342.63,5773.06 R104.1@14342.63,5851.06
  Component Side w20: R103.1@14342.63,5773.06 RS485_2.1@14923.63,5773.06
NetR103_2: R103.2 R105.1 RS485_2.2 U45.6 | length 811.4
  Component Side w10: U45.6@14203.42,5714.52 R103.2@14338.18,5714.52 ; R105.1@14342.63,5628.06 R103.2@14342.63,5710.07
  Component Side w20: R103.2@14342.63,5710.07 RS485_2.2@14937.29,5710.07
NetR136_1: R136.1 S2.3 | length 121.4
  Component Side w10: S2.3@10480.16,6014.28 R136.1@10480.16,6135.68
NetR137_1: R137.1 S4.3 | length 165
  Component Side w10: S4.3@10488.95,7012.31 R137.1@10488.95,7177.35
NetU1_5: U1.5 X1.1 | length 488.3
  Component Side w10: U1.5@13757.51,6855.25 13757.51,6912.35 13828.5,6983.34 13893.52,6983.34 13946.36,7036.17 X1.1@13946.36,7227.19
NetU23_6: U23.6 U23.7 | length 51.6
  Component Side w10: U23.6@11279.24,7880.35 U23.6@11279.24,7881.52 U23.7@11279.24,7931.92
NULL: C47.1 U14.7 | length 101.8
  Component Side w10: C47.1@11896.7,7709.05 11901.69,7709.05 11928.94,7736.31 U14.7@11987.2,7736.31
R_VOLTAGE: K12.6 R49.2 T1.1 U6.7 | length 5877.8
  Component Side w10: R49.2@10302.51,6347.69 v3(10433.81,6347.69)
  Component Side w20: U6.7@8333.64,8932.11 T1.1@8534.73,8932.11 ; v3(8536.47,9499.16) v3@10138.1,9499.16
  Solder Side w20: T1.1@8535.82,8933.06 v3@8535.82,9498.18 ; v3(10141.8,9500.2) 10141.8,8760.21 10269.76,8632.25 K12.6@10439.07,8632.25 ; K12.6@10432.51,8632.18 10435.51,8629.18 10433.95,8627.62 10434.21,8627.36 v3@10434.21,6345.84
RG1+: K13.6 U6.2 | length 3725.4
  Component Side w10: v3@7602.82,8932.11 U6.2@8117.1,8932.11
  Component Side w20: v3@7596.22,6281.31 8021.37,6281.31 K13.6@8114.82,6187.86
  Solder Side w20: v3@7601.38,6279.82 7602.02,6280.46 v3(7602.02,8933.32)
  other v3: 7601.19,6281.59
RG1-: R44.2 U6.3 | length 111.3
  Component Side w10: R44.2@8009.69,8891.08 8067.04,8891.08 8076.4,8881.72 U6.3@8117.1,8881.72
RG2+: K14.6 U7.2 | length 1843.5
  Component Side w20: v3@7787.9,6662.95 8029.27,6662.95 8116.68,6575.54 K14.6@8116.68,6562.69 ; v3@7792.74,7798.88 U7.2@8123.04,7798.88
  Solder Side w20: v3@7791.8,6665.94 v3@7791.8,7801.25
  other v3: 7789.41,6665.98 7791.6,7799.68
RG2-: R45.2 U7.3 | length 112.8
  Component Side w10: R45.2@8010.19,7748.49 U7.3@8123.04,7748.49
RS485_RE: U1.58 U44.2 U44.3 | length 1154.9
  Component Side w10: U1.58@13907.11,6666.27 14341.06,6666.27 v3@14368.45,6693.66 ; v1(14551.88,6209.52) U44.3@14621.88,6209.52 ; U44.3@14621.88,6205.31 U44.3@14621.88,6209.52 ; U44.2@14621.88,6255.7 U44.3@14621.88,6209.52
  Solder Side w10: v3@14367.17,6695.79 14367.17,6390.02 v1@14547.67,6209.52 ; v1(14551.88,6209.52) v1@14551.88,6210.31
  other v3: 14367.59,6695.36
RS485_RE2: U1.39 U45.2 U45.3 | length 1056.4
  Component Side w10: U1.39@13659.08,6418.24 13659.08,5758.11 13702.67,5714.52 U45.3@13986.88,5714.52 U45.2@13986.88,5764.91
S1_CTRL: S1.1 U1.59 | length 6815.9
  Component Side w10: S1.1@10405.49,5977.12 10435.82,5946.78 v1(10435.82,5898.94) ; v1@10434.5,5107.37 14343.53,5107.37 v1(14344.33,5108.17) ; U1.59@13907.11,6685.96 14244.31,6685.96 v1@14280.82,6722.46
  Solder Side w10: v1(10435.07,5107.25) v1@10435.07,5892.14 ; v1(14281.8,6723.35) 14281.8,6357.11 14344.13,6294.77 v1@14344.13,5107.93
S2_CTRL: S2.1 U1.61 | length 6999.8
  Component Side w10: v1(10581.66,5921.63) S2.1@10581.66,5978.95 ; v1@10582.67,5075.41 v1(14439.11,5075.41) ; U1.61@13907.11,6725.33 14002.4,6725.33 14041.9,6764.83 14228.73,6764.83 14276.27,6812.37 v1@14314.83,6812.37
  Solder Side w10: v1@10582.13,5921.78 v1(10582.13,5074.62) v1@10588.2,5080.69 ; v1(14323.25,6813.25) 14323.25,6371.55 14438.26,6256.53 v1@14438.26,5074.38
S3_CTRL: S3.1 U1.62 | length 7787.2
  Component Side w10: v1@10391.6,5148.53 v1(14286.3,5148.53) ; v1@10392.2,6908.39 S3.1@10392.2,6982.64 ; U1.62@13907.11,6745.01 13986.26,6745.01 14028.82,6787.57 14195.89,6787.57 v1@14233.69,6825.36
  Solder Side w10: v1@10391.83,5148.52 v1@10391.83,6907.82 ; v1(14231.66,6825.51) 14231.66,6334.2 14285.5,6280.36 v1@14285.5,5148.7
  other v1: 10392.13,5147.6 10391.83,6911.6
S4_CTRL: S4.1 U1.34 | length 3765.6
  Component Side w10: v1@10582.22,6417.62 10583.15,6418.54 12407.79,6418.54 12606.51,6219.83 13474.99,6219.83 13560.66,6305.49 U1.34@13560.66,6418.24 ; v1(10586.5,6913.26) S4.1@10586.5,6972.64
  Solder Side w10: v1(10587.09,6418.02) v1@10587.09,6914.86
SENSE_H: R14.1 R76.2 SENSE_H.1 | length 1582.1
  Component Side w10: SENSE_H.1@7285.9,8111.41 R76.2@7285.9,8711.05
  Component Side w20: SENSE_H.1@7283.57,8111.41 7283.57,7883.49 7505.77,7661.29 R14.1@7946.08,7661.29
SENSE_L: R12.1 R75.1 SENSE_L.1 | length 2097.8
  Component Side w10: R75.1@7295.36,6388.03 SENSE_L.1@7295.36,6937.6
  Component Side w20: SENSE_L.1@7295.36,6937.6 v2@7709.54,6937.6 ; v3@7722.87,7852.88 R12.1@7943.27,7852.88
  Solder Side w20: v2(7715.75,6933.67) v3@7715.75,7847.31
  other v3: 7713.8,7855.09
SIGIN: C154.2 R25.2 T3.1 U3.3 U23.1 | length 1786.5
  Component Side w10: U23.1@11062.71,7982.31 11104.87,7982.31 11126.87,8004.31 11126.87,8172.08 R25.2@11123.61,8172.08
  Component Side w20: R25.2@11126.87,8172.08 v2@11404.28,8172.08 ; T3.1@11405.62,9082.32 U3.3@11762.79,9082.32
  Solder Side w20: v2@11405.15,8172.62 T3.1@11405.15,9080.27
  other v2: 11408.11,8171.77
SIGOUT: C48.1 R24.1 U14.3 | length 1862.5
  Component Side w10: v1@10737.06,7960.42 R24.1@10828.57,7960.42 ; v1@10741.06,7541.05 11470.53,7541.05 11582.09,7652.61 11582.09,7653.24 11691.73,7762.88 11852.24,7762.88 C48.1@11901.49,7812.12 ; C48.1@11909.65,7820.6 11926.15,7837.1 U14.3@11987.2,7837.1
  Solder Side w10: v1@10737.46,7957.73 10737.55,7957.64 v1(10737.55,7544.22)
  other v1: 10736.36,7960.72
SWCLK: DL.2 U1.49 | length 4319.2
  Component Side w10: U1.49@13907.11,6489.11 14448.63,6489.11 14577.6,6618.08 14577.6,9159.16 14688.75,9270.31 DL.2@15575.29,9270.31 ; DL.2@15565.53,9270.19 DL.2@15576,9270.19
SWDIO: DL.3 DL.4 U1.46 | length 5003
  Component Side w10: U1.46@13796.88,6418.24 13796.88,6236.03 13847.6,6185.31 14286.88,6185.31 14613.48,6511.9 14613.48,9081.9 14660.14,9128.57 15587.95,9128.57 15642.68,9183.3 15642.68,9215.5 15642.78,9215.6 15642.78,9280.98 15627.98,9295.78 15565.53,9295.78 DL.4@15565.53,9321.37
UART3_RX: LCD.5 U1.30 | length 3147.3
  Component Side w10: v1@13063.94,6463.87 13132.9,6463.87 13197.5,6528.48 U1.30@13470.11,6528.48
  Solder Side w10: v1@13063.78,6460.29 13063.78,8886.65 13063.51,8886.93 LCD.5@13266.88,9090.31
  other v1: 13064.82,6462.05
UART3_TX: LCD.3 LCD.4 U1.29 | length 2919.2
  Component Side w10: v1@13113.3,6512.03 13142.34,6512.03 13178.47,6548.16 U1.29@13470.11,6548.16
  Solder Side w10: v1@13109.67,6511.3 13109.67,8732.9 LCD.3@13269.37,8892.61 ; LCD.3@13266.88,8890.31 LCD.4@13266.88,8990.31
  other v1: 13111.49,6511.41
USART1_RX: U1.43 U44.1 | length 1262.7
  Component Side w10: U1.43@13737.82,6418.24 13737.82,6159.37 13806.88,6090.31 14321.88,6090.31 14541.88,6310.31 U44.1@14621.88,6310.31
USART1_TX: U1.42 U44.4 | length 1257
  Component Side w10: U1.42@13718.14,6418.24 13718.14,6139.06 13796.88,6060.31 14336.88,6060.31 14436.88,6160.31 U44.4@14621.88,6160.31
USART2_RX: U1.17 U45.1 | length 2545.9
  Component Side w10: v1@12943.06,6863.92 13344.23,6863.92 13423.77,6784.38 U1.17@13470.11,6784.38 ; v1@13710.87,5815.31 U45.1@13986.88,5815.31
  Solder Side w10: v1@12943.74,6863.7 12943.74,5981.84 13110.85,5814.73 ; 13112.12,5815.06 v1@13703.87,5815.06
  other v1: 13705.53,5814.43 12943.06,6862.53
USART2_TX: U1.16 U45.4 | length 2812.1
  Component Side w10: v1@12898.42,6911.01 13352.49,6911.01 13408.25,6855.25 U1.16@13540.97,6855.25 ; v1@13701.63,5664.13 U45.4@13986.88,5664.13
  Solder Side w10: v1(12899.83,6912.23) 12899.83,5972.48 13209.47,5662.84 v1@13692.98,5662.84
  other v1: 13698.23,5662.68
USB_DM: R43.2 U1.44 | length 3171.6
  Component Side w10: U1.44@13757.51,6418.24 13757.51,6179.69 13816.88,6120.31 14311.88,6120.31 14686.51,6494.94 14686.51,8189.94 14730.28,8233.71 R43.2@14797.67,8233.71
USB_DP: R41.2 R42.2 U1.45 | length 3241.1
  Component Side w10: U1.45@13777.19,6418.24 13777.19,6205 13831.88,6150.31 14296.88,6150.31 14656.62,6510.05 14656.62,8244.01 14727.9,8315.29 ; 14726.88,8315.31 R41.2@14796.88,8315.31 ; R41.2@14797.69,8317.87 R42.2@14797.69,8389.88
pads on no net: DL.1 J1.1 J1.4 J1.6 J1.7 J1.8 J1.9 J1.10 J1.11 K1.2 K1.7 K2.2 K2.7 K3.2 K3.7 K4.2 K4.7 K5.2 K5.7 K6.2 K6.7 K7.2 K7.7 K8.2 K8.7 K9.2 K9.7 K10.2 K10.7 K11.3 K11.6 K12.4 K13.1 K13.4 K14.1 K14.4 K15.3 LCD.6 U1.2 U1.3 U1.4 U1.7 U1.50 U12.1 U12.3 U12.5 U12.7 U12.8 U14.2 U14.6 U14.8 U17.7 U18.7 USB.1
copper on no net:
  other v4: 15606,9200.31 15606,9391.25
  other v5: 15711.51,9153.06 15711.51,9438.5

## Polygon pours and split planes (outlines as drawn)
DGND on Component Side "Top Side-DGND" (solid, remove dead copper, pour order 6): 12831.55,9643.63 12363.43,9175.51 12363.43,9105.3 12363.43,4861 12363.44,4860.98 12363.61,4860.81 15663.08,4860.81 15663.2,4860.81 15750.41,4948.02 15750.02,4948.41 15750.02,9643.92
AGND on Component Side "Top Side-AGND" (solid, remove dead copper, pour order 2): 7128.4,12257.77 7128.72,12257.45 7128.72,4860.71 12332.76,4860.71 12332.84,4860.64 12332.98,4860.78 12332.98,9190.76 12335.4,9190.76 12818.88,9674.24 12819.04,9674.08 15750.06,9674.08 15750.06,12172.67 15664.58,12258.15
DGND on Solder Side "Bot Side-DGND" (solid, remove dead copper, pour order 8): 12831.55,9643.63 12363.43,9175.51 12363.43,9105.3 12363.43,4861 12363.44,4860.98 12363.61,4860.81 15663.08,4860.81 15663.2,4860.81 15750.41,4948.02 15750.02,4948.41 15750.02,9643.92
AGND on Solder Side "Bot Side-AGND" (solid, remove dead copper, pour order 4): 7128.4,12257.77 7128.72,12257.45 7128.72,4860.71 12332.76,4860.71 12332.84,4860.64 12332.98,4860.78 12332.98,9190.76 12335.4,9190.76 12818.88,9674.24 12819.04,9674.08 15750.06,9674.08 15750.06,12172.67 15664.58,12258.15
DGND on Ground Plane (split plane): 15749.96,4947.73 15663.31,4861.08 12362.7,4861.08 12362.7,9175.54 12831.17,9644.02 15749.96,9644.02
AGND on Ground Plane (split plane): 15749.96,12171.24 15749.96,9674.16 12822.63,9674.16 12819.69,9673.87 12816.86,9673.02 12814.25,9671.62 12811.97,9669.75 12810.09,9667.46 12808.7,9664.86 12808.41,9663.88 12342.84,9198.31 12341.86,9198.02 12339.25,9196.62 12336.97,9194.75 12335.09,9192.46 12333.7,9189.86 12332.84,9187.03 12332.55,9184.09 12332.55,4861.08 7128.74,4861.08 7128.74,12257.89 15663.31,12257.89
D3V3 on Power Plane (split plane): 15749.96,4947.73 15663.31,4861.08 12357.7,4861.08 12357.7,9168.4 12358.41,9168.98 12828.45,9639.02 15749.96,9639.02
AGND on Power Plane (split plane): 15749.96,12171.24 15749.96,9669.16 12826.55,9669.16 12825.69,9669.42 12822.75,9669.71 12819.81,9669.42 12818.96,9669.16 12817.63,9669.16 12814.69,9668.87 12811.86,9668.02 12809.25,9666.62 12806.97,9664.75 12805.09,9662.46 12803.7,9659.86 12802.84,9657.03 12802.74,9655.94 12340.78,9193.98 12339.69,9193.87 12336.86,9193.02 12334.25,9191.62 12331.97,9189.75 12330.09,9187.46 12328.7,9184.86 12327.84,9182.03 12327.55,9179.09 12327.55,4861.08 7128.74,4861.08 7128.74,12257.89 15663.31,12257.89

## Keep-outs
Keep-Out Layer:
  circle w10: c15662.11,12059.17 r53.15
  circle w10: c7249.91,12059.17 r53.15
  circle w10: c7249.91,5059.17 r53.15
  circle w10: c15662.11,5059.17 r53.15
  lines w10: 7108.64,4840.98 15671.64,4840.98 15770.06,4939.41 15770.06,12179.56 15671.64,12277.99 7108.64,12277.99 ; 7109.36,4840.67 7109.36,12277.67 15672.35,12277.67 15770.77,12179.25 15770.77,4939.09 15672.35,4840.67 7109.36,4840.67

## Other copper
Component Side:
  rectangle net DGND: 13231.88,8660.31 13471.88,8820.31
  rectangle net DGND: 13749.93,8724.48 13812.45,8734.68
  rectangle net D3V3: 13936.88,8795.31 14131.88,8960.31
  rectangle net DGND: 13749.93,8734.68 13812.45,8781.97
  pour cut-out: 7109.26,5210.29 7109.26,4840.74 7399.26,4840.74 7399.26,5210.29
  pour cut-out: 7108.13,12278.06 7108.13,11908.51 7398.13,11908.51 7398.13,12278.06
  pour cut-out: 15481.13,12278.36 15481.13,11908.82 15771.13,11908.82 15771.13,12278.36
  pour cut-out: 15478.67,5210.53 15478.67,4840.98 15768.67,4840.98 15768.67,5210.53
Ground Plane (plane layer: these items are gaps in the copper):
  lines w30: 12347.63,4839.33 12347.63,9184.09 ; 12349.72,9183.88 12824.72,9658.88 ; 12822.63,9659.09 15774.48,9659.09
Power Plane (plane layer: these items are gaps in the copper):
  lines w30: 12342.63,4847.86 12342.63,9179.09 ; 12347.75,9179.64 12822.75,9654.64 ; 12817.63,9654.09 15765.07,9654.09

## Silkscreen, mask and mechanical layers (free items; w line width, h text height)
Top Overlay:
  drawing of 4930 lines, arcs and shapes, not listed
  text "+" at 7169.89,11253.52 h30
  text "+" at 7167.27,10783.24 h30
  text "SMU_V2.01_03222018" at 13967.4,10274.53 h100
  text "+" at 13148.92,9372.62 h30
  text "-" at 13149.8,8667.44 h30
Mechanical 1:
  circle w10: c15662.11,12059.17 r53.15
  circle w10: c7249.91,12059.17 r53.15
  circle w10: c7249.91,5059.17 r53.15
  circle w10: c15662.11,5059.17 r53.15
  lines w10: 7109.36,4840.67 15672.35,4840.67 15770.77,4939.09 15770.77,12179.25 15672.35,12277.67 7109.36,12277.67 7109.36,4840.67

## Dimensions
7102.28,4635.66 to 15764.65,4593.54 on Top Overlay
15908.52,4838.09 to 16089.02,12280.74 on Top Overlay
